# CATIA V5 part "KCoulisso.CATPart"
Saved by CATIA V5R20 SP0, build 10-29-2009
Part number: K_Coulisso
Bounding box of the stored display mesh (mm): x -20 to 24, y 115.705 to 135.662, z 554.501 to 600.228
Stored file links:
  C:\Users\thinkmotion1\Desktop\Khaled_IAO_Pack2\IAO_2010_1392_rragonneau\CATIA_1392_rragonneau\KCoulisso.CATPart
  D:\Documents\Scolaire\MM2\IAO\Squelette\Product1.CATProduct
  C:\Users\thinkmotion1\Desktop\Khaled_IAO_Pack2\IAO_2010_1392_rragonneau\CATIA_1392_rragonneau\KSquelette de base.CATPart
  C:\Users\thinkmotion1\Desktop\Khaled_IAO_Pack2\Problemes\IAO_2010_1392_rragonneau\Bielle.CATPart
  C:\Users\ThinkMotion\Desktop\EU_thinkMotion\iao\IAO_MMS_Groupe1\Problemes\rragonneau\rragonneau\Squelette coulisso.CATPart
  C:\Users\ThinkMotion\Desktop\EU_thinkMotion\iao\IAO_MMS_Groupe1\Problemes\rragonneau\rragonneau\Squelette bati.CATPart
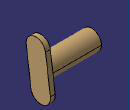
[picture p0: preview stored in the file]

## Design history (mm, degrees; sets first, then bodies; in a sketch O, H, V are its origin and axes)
Set1
  Sketch1 on Plane1, origin (0, 0, 0), H (0, 1, 0), V (0, 0, 1)
    circle A1 centre (125.683, 577.3649) radius 8
    radius A1 = 8
Set2
  Plane1: linked copy from another document
Body1 (main body)
  Pad1: profile Sketch1, direction (1, 0, 0), length 20, opposite side length 20
  Sketch2 on end face of Pad1, origin (20, 0, 0), H (0, 1, 0), V (0, 0, 1)
    construction line L1 (123.6998, 592.2332) -> (127.6663, 562.4965)
    line L2 (131.6295, 593.2909) -> (135.596, 563.5543)
    line L3 (119.7365, 561.4388) -> (115.77, 591.1754)
    arc A1 centre (127.6663, 562.4965) radius 8 from (135.596, 563.5543) to (119.7365, 561.4388) cw
    arc A2 centre (123.6998, 592.2332) radius 8 from (115.77, 591.1754) to (131.6295, 593.2909) cw
    axis line L4 (94.9534, 588.3988) -> (155.5402, 596.4803)
    distance L3 L2 = 16
    distance A1 A2 = 46
    tangency: A1 L2, A2 L2, A1 L3, A2 L3
  Pad2: profile Sketch2, direction (1, 0, 0), length 4
  Point1: type Center, Curve edge [start face of Pad1 | face of Pad1 from Sketch1.A1]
